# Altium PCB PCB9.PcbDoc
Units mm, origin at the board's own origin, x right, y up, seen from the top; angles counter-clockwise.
Board outline 101.6 x 53.34 mm, 4 copper layers (TOP, GND, SIG, BOTTOM), stack 1.586 mm thick; 105 components, 243 nets, 863 pads, 0 vias.
Unrouted connection lines stored in the file: 305.
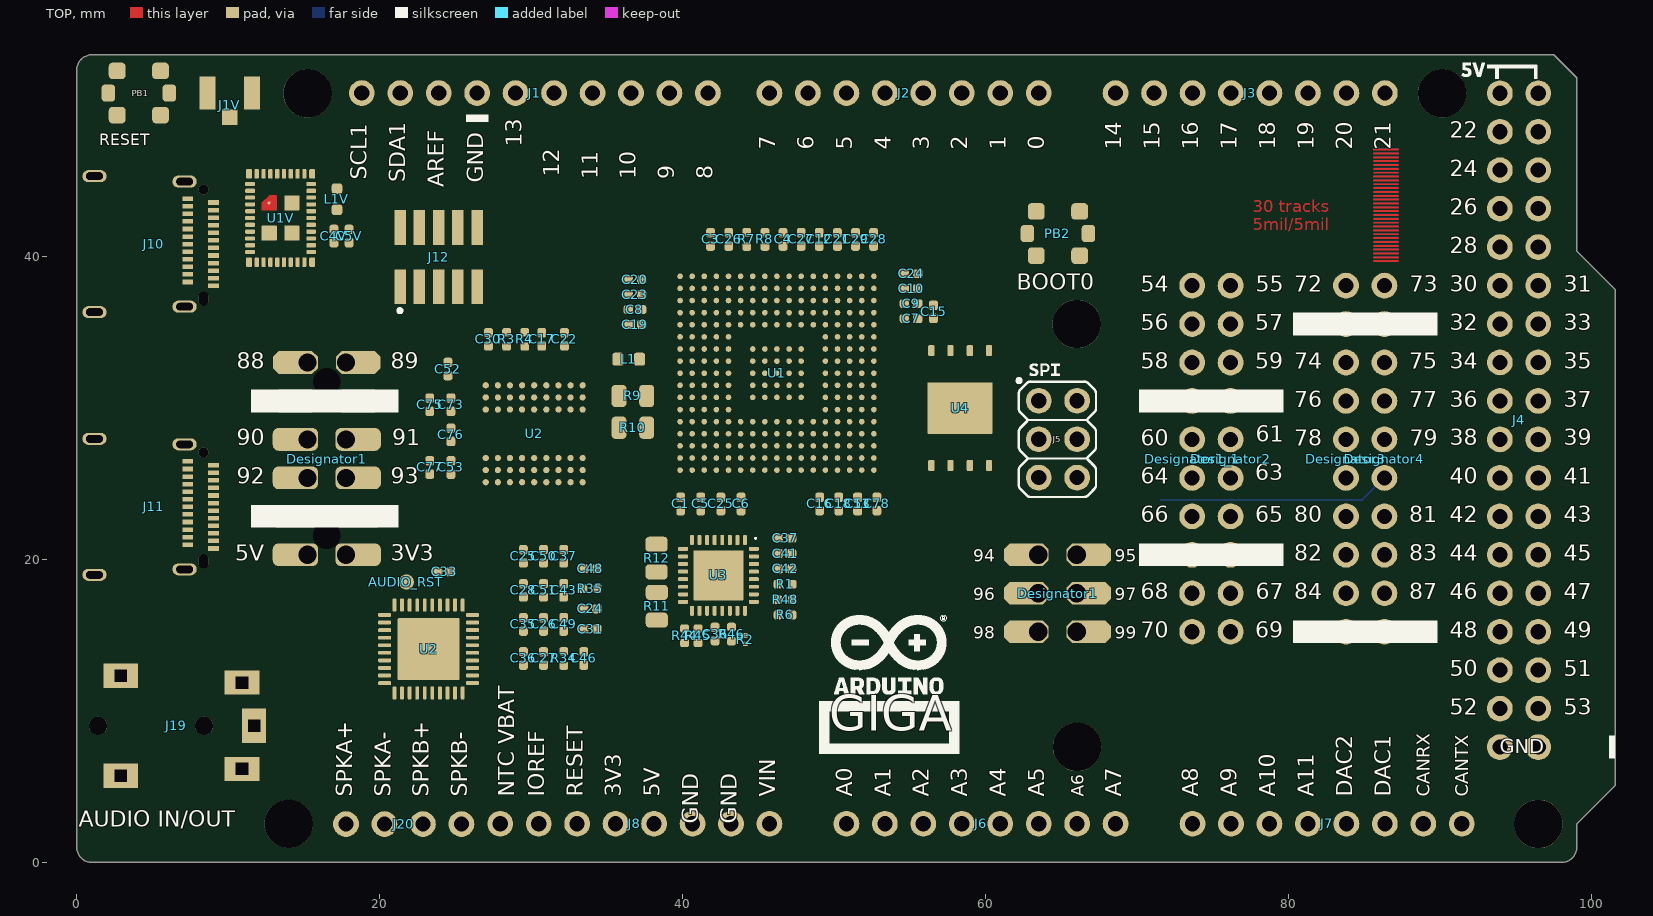
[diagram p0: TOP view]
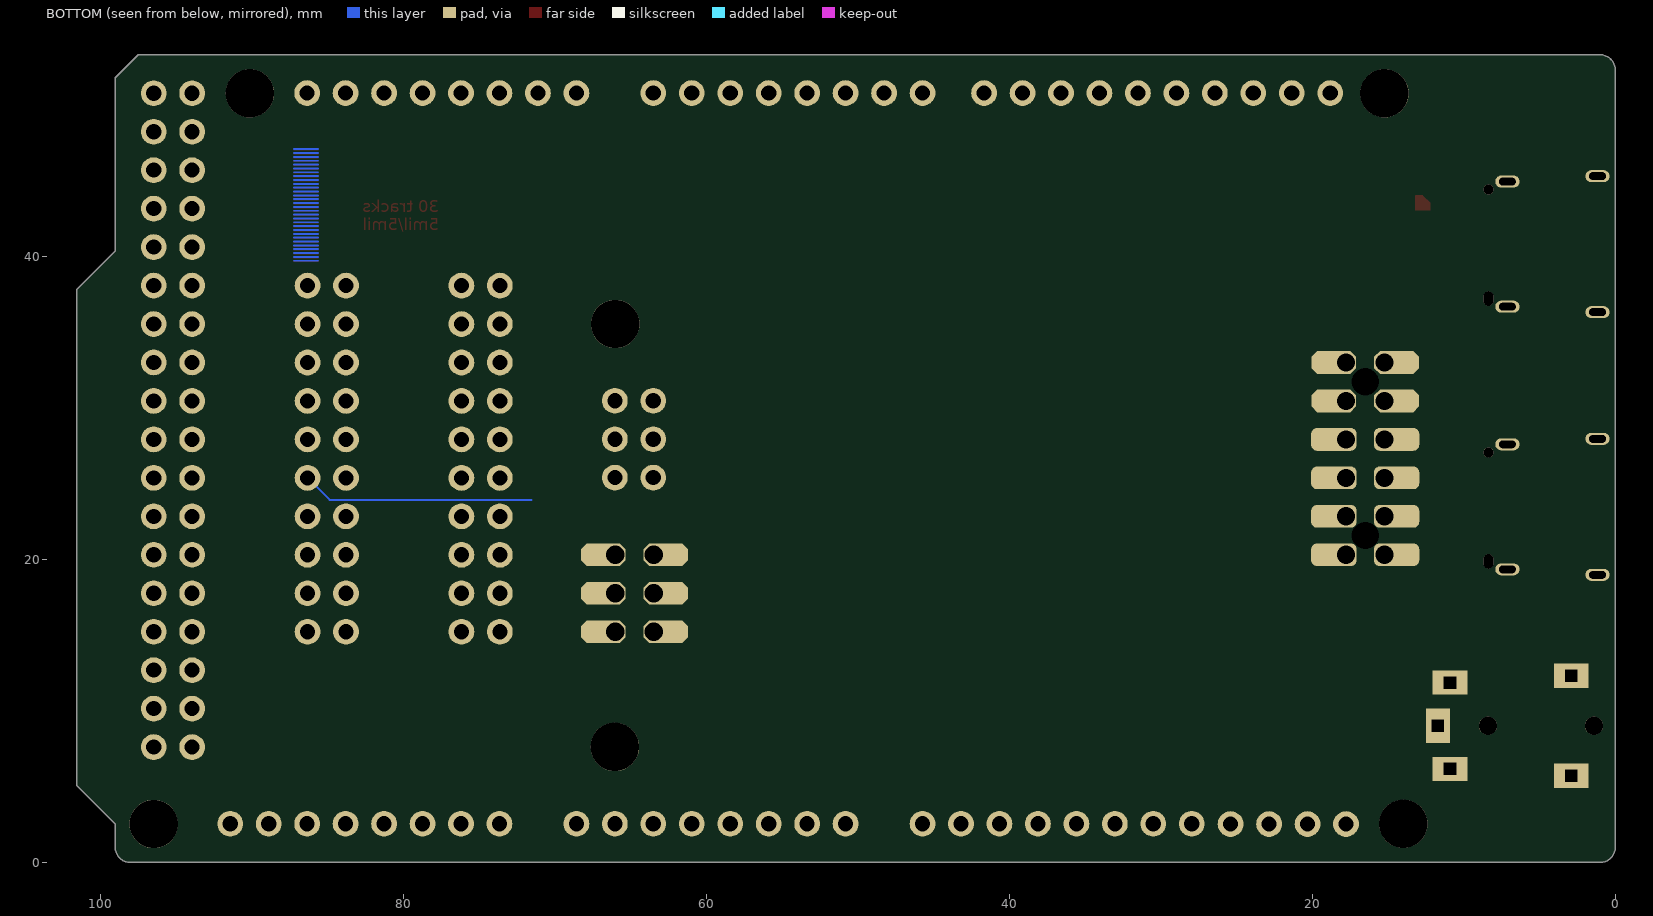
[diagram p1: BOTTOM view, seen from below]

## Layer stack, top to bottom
Top Solder: solder mask 0.0102, Solder Resist, Dk 3.5
TOP: signal copper 0.018
Dielectric 1: prepreg 0.14, PP-014, Dk 4.2
GND: signal copper 0.035
Dielectric2: core 1.2, FR-4, Dk 4.8
SIG: signal copper 0.035
Dielectric3: prepreg 0.14, PP-014, Dk 4.2
BOTTOM: signal copper 0.018
Bottom Solder: solder mask 0.0102, Solder Resist, Dk 3.5

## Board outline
0,1 0,52.34 cw(c1,52.34) 1,53.34 97.536,53.34 99.06,51.816 99.06,40.386 101.6,37.846 101.6,5.08 99.06,2.54 99.06,1 cw(c98.06,1) 98.06,0 1,0 cw(c1,1)

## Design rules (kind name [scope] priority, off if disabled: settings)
BoardOutlineClearance Silks [(OnLayer('Top Overlay') OR OnLayer('Bottom Overlay'))] p1: gap=0.1 ignorepadtopadclearanceinfootprint=FALSE
BoardOutlineClearance [All] p2: gap=0.3 ignorepadtopadclearanceinfootprint=FALSE
Clearance COPPER_0.3mm [All] p1: gap=0.127 ignorepadtopadclearanceinfootprint=FALSE except(0.3: Arc-Fill Arc-Poly Arc-Region Track-Fill Track-Poly Track-Region SMDPad-Fill SMDPad-Poly SMDPad-Region THPad-Fill THPad-Poly THPad-Region Via-Fill Via-Poly Via-Region Fill-Fill Fill-Poly Fill-Region Poly-Poly Poly-Region Region-Region)
Clearance "Generic clearance 0.127mm" [All] p2: gap=0.127 ignorepadtopadclearanceinfootprint=FALSE
ComponentClearance [All] p1: gap=0.2 collisioncheckmode=3 verticalgap=0 showdistances=TRUE
DiffPairsRouting USB [InDifferentialPairClass('USB')] p1: maxlimit=0.254 minlimit=0.15 mostfreqgap=0.254 toplayer_maxgap=0.15 toplayer_prefgap=0.15 toplayer_minwidth=0.15 toplayer_maxwidth=0.21 toplayer_prefwidth=0.2 midlayer2_mingap=0.24 midlayer2_maxgap=0.24 midlayer2_prefgap=0.24 midlayer2_minwidth=0.15 midlayer2_maxwidth=0.15 midlayer2_prefwidth=0.15 bottomlayer_maxgap=0.15 bottomlayer_prefgap=0.15 bottomlayer_minwidth=0.15 bottomlayer_maxwidth=0.21 bottomlayer_prefwidth=0.2 impedanceprofiledriven=TRUE impedanceprofileid={E6B00C31-4C8E-439C-824F-D2B2CDC26F9C} impedanceprofilevalue=90.000000 maxuncoupledlength=12.7
Height [All] p1: minheight=0 maxheight=30 prefheight=12.7
HoleSize [All] p1: absolutevalues=TRUE maxlimit=20 minlimit=0.3 maxpercent=80.000 minpercent=20.000
HoleToHoleClearance [All] p1: gap=0.25 allowstackedmicrovias=FALSE
MinimumAnnularRing [All] p1: minimumring=0.15
PlaneConnect [All] p1: pad.planeconnectstyle=Relief pad.reliefexpansion=0.508 pad.reliefentries=4 pad.reliefconductorwidth=0.254 pad.reliefairgap=0.254 via.planeconnectstyle=Direct via.reliefexpansion=0.508 via.reliefentries=4 via.reliefconductorwidth=0.254 via.reliefairgap=0.254
PolygonConnect [All] p1: thpad.connectstyle=Relief thpad.reliefconductorwidth=0.2 thpad.reliefentries=4 thpad.polygonreliefangle="90 Angle" thpad.airgapwidth=0.254 smdpad.connectstyle=Relief smdpad.reliefconductorwidth=0.2 smdpad.reliefentries=4 smdpad.polygonreliefangle="90 Angle" smdpad.airgapwidth=0.254 via.connectstyle=Direct via.reliefconductorwidth=0.254 via.reliefentries=4 via.polygonreliefangle="90 Angle" via.airgapwidth=0.254
RoomDefinition AUDIO [InComponentClass('AUDIO')] p1: confinementstyle=ConfineIn formatcopy=TRUE lockcomponents=FALSE outline 102.7,0.5 179.2,0.5 179.2,30 102.7,30
RoomDefinition Wifi [InComponentClass('Wifi')] p2: confinementstyle=ConfineIn formatcopy=TRUE lockcomponents=FALSE outline -40.4,-40.4 10.4,-40.4 10.4,-15 -40.4,-15
RoomDefinition TOP [InComponentClass('TOP')] p3: confinementstyle=ConfineIn formatcopy=TRUE lockcomponents=FALSE outline 102.7,1.5 112.4,1.5 112.4,12.5 102.7,12.5
RoomDefinition HEADERS [InComponentClass('HEADERS')] p4: confinementstyle=ConfineIn formatcopy=TRUE lockcomponents=FALSE outline 103.6,3.6 145.6,3.6 145.6,51.6 103.6,51.6
RoomDefinition STM32H747 [InComponentClass('STM32H747')] p5: confinementstyle=ConfineIn formatcopy=TRUE lockcomponents=FALSE outline 57.6,-10.4 61.6,-10.4 61.6,-6.4 57.6,-6.4
RoutingVias StandardVias [All] p1: holewidth=0.2 width=0.4 viastyle="Through Hole" minholewidth=0.2 minwidth=0.4 maxholewidth=0.2 maxwidth=0.4
SMDToCorner [All] p1: distance=39370
SilkToSilkClearance [All] p1: silktosilkclearance=0.2
SilkToSolderMaskClearance [IsPad] p1: minsilkscreentomaskgap=0.15 clearancetoexposedcopper=TRUE
SolderMaskExpansion VIAtented [IsVia] p1: expansion=0.102 istentingtop=TRUE
SolderMaskExpansion [All] p2: expansion=0.05 istentingtop=FALSE
UnRoutedNet [All] p1: checkbadconnections=TRUE
ViasUnderSMD [All] p1: allowed=FALSE
Width StandardTraces [All] p1: maxlimit=5 minlimit=0.127 preferedwidth=0.15
21 further rules are at their usual default settings.

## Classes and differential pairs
component class AUDIO: AUDIO_RST C24 C25 C26 C27 C28 C31 C33 C35 C36 C37 C43 C46 C48 C49 C50 C51 J19 R34 R35 U2
net class "50 ohm": NetC1V_1 NetC2V_1
component class Wifi: R18
component class TOP: PB2
component class HEADERS: J1 J2 J3 J4 J5 J6 J7 J8 J12 J20
component class STM32H747: C1 C3 C4 C5 C6 C7 C8 C9 C10 C12 C13 C15 C16 C17 C18 C19 C20 C21 C22 C23 C24 C25 C26 C27 C28 C29 C30 C36 C37 C41 C42 C51 C52 C53 C73 C75 C76 C77 C78 L1 R1 R2 R3 R4 R6 R7 R8 R9 R10 R11 R12 R44 R45 R46 R48 U1 U2 U3 U4

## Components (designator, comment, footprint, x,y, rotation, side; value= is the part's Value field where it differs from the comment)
AUDIO_RST "CMP-018-0005-A.3" TP-1.00MM 21.77,18.519 r180 top
C1 "CBR04C220F5GAC" CAP-0402 39.88,23.675 r90 top value=22pF
C3 "GRM155R60J106ME05D" CAP-0402 41.859,41.145 r270 top value=10µF
C4 "GRM155R60J225KE95D" CAP-0402 46.644,41.145 r270 top value=2.2µF
C4V "GRM155R60J475ME47D" CAP-0402 16.984,41.367 r270 top value=4.7µF
C5 "GRM155R60J225KE95D" CAP-0402 41.21,23.675 r90 top value=2.2µF
C5V "GRM155R60J475ME47D" CAP-0402 17.984,41.367 r270 top value=4.7µF
C6 "GRM155R60J225KE95D" CAP-0402 43.87,23.675 r90 top value=2.2µF
C7 "GRM155R61H104KE19D" CAP-0402 55.097,35.913 r0 top value=100nF
C8 "GRM155R61H104KE19D" CAP-0402 36.865,36.51 r0 top value=100nF
C9 "GRM155R61H104KE19D" CAP-0402 55.097,36.903 r0 top value=100nF
C10 "GRM155R61H104KE19D" CAP-0402 55.097,37.893 r0 top value=100nF
C12 "CBR04C220F5GAC" CAP-0402 49.036,41.145 r270 top value=22pF
C13 "GRM155R61H104KE19D" CAP-0402 51.581,23.675 r270 top value=100nF
C15 "GRM155R61H104KE19D" CAP-0402 56.579,36.36 r90 top value=100nF
C16 "GRM155R61H104KE19D" CAP-0402 49.06,23.675 r270 top value=100nF
C17 "GRM155R61H104KE19D" CAP-0402 30.709,34.545 r90 top value=100nF
C18 "GRM155R61H104KE19D" CAP-0402 50.321,23.675 r270 top value=100nF
C19 "GRM155R61H104KE19D" CAP-0402 36.865,35.52 r0 top value=100nF
C20 "GRM155R61H104KE19D" CAP-0402 36.865,38.49 r0 top value=100nF
C21 "GRM155R61H104KE19D" CAP-0402 50.232,41.145 r270 top value=100nF
C22 "GRM155R61H104KE19D" CAP-0402 32.209,34.545 r90 top value=100nF
C23 "GRM155R61H104KE19D" CAP-0402 36.865,37.5 r0 top value=100nF
C24 "C0402C105K8PACTU" CAP-0402 33.915,16.74 r180 top value=1µF
C24 "GRM155R61H104KE19D" CAP-0402 55.097,38.883 r0 top value=100nF
C25 "C0402C104K4RACTU" CAP-0402 29.496,20.22 r90 top value=100nF
C25 "GRM155R60J225KE95D" CAP-0402 42.54,23.675 r90 top value=2.2µF
C26 "C0402C104K4RACTU" CAP-0402 30.826,15.72 r90 top value=100nF
C26 "GRM155R60J225KE95D" CAP-0402 43.055,41.145 r270 top value=2.2µF
C27 "C0402C104K4RACTU" CAP-0402 30.826,13.47 r90 top value=100nF
C27 "GRM155R60J225KE95D" CAP-0402 47.84,41.145 r270 top value=2.2µF
C28 "C0402C105K8PACTU" CAP-0402 29.496,17.97 r90 top value=1µF
C28 "GRM155R61H104KE19D" CAP-0402 52.625,41.145 r270 top value=100nF
C29 "GRM155R61H104KE19D" CAP-0402 51.429,41.145 r270 top value=100nF
C30 "GRM155R60J106ME05D" CAP-0402 27.188,34.545 r270 top value=10µF
C31 "C0402C105K8PACTU" CAP-0402 33.915,15.41 r180 top value=1µF
C33 "C0402C105K8PACTU" CAP-0402 24.257,19.185 r180 top value=1µF
C35 "C0402C104K4RACTU" CAP-0402 29.496,15.72 r90 top value=100nF
C36 "C0402C104K4RACTU" CAP-0402 29.496,13.47 r90 top value=100nF
C36 "GRM155R61H104KE19D" CAP-0402 42.155,15.085 r90 top value=100nF
C37 "C0402C104K4RACTU" CAP-0402 32.156,20.22 r90 top value=100nF
C37 "GRM155R61H104KE19D" CAP-0402 46.775,21.41 r180 top value=100nF
C41 "GRM155R61H104KE19D" CAP-0402 46.775,20.397 r180 top value=100nF
C42 "GRM155R61H104KE19D" CAP-0402 46.775,19.383 r180 top value=100nF
C43 "C0402C104K4RACTU" CAP-0402 32.156,17.97 r90 top value=100nF
C46 "GRM1555C1H151FA01D" CAP-0402 33.486,13.47 r90 top value=150pF
C48 "C0402C104K4RACTU" CAP-0402 33.915,19.4 r180 top value=100nF
C49 "C0402C105K8PACTU" CAP-0402 32.156,15.72 r90 top value=1µF
C50 "GRM1555C1H151FA01D" CAP-0402 30.826,20.22 r90 top value=150pF
C51 "C0402C104K4RACTU" CAP-0402 30.826,17.97 r90 top value=100nF
C51 "GRM155R61H104KE19D" CAP-0402 51.563,23.675 r270 top value=100nF
C52 "GRM155R61H104KE19D" CAP-0402 24.512,32.585 r90 top value=100nF
C53 "GRM155R61H104KE19D" CAP-0402 24.712,26.085 r270 top value=100nF
C73 "GRM155R61H104KE19D" CAP-0402 24.712,30.23 r90 top value=100nF
C75 "GRM155R61H104KE19D" CAP-0402 23.312,30.23 r270 top value=100nF
C76 "GRM155R61H104KE19D" CAP-0402 24.712,28.24 r90 top value=100nF
C77 "GRM155R61H104KE19D" CAP-0402 23.312,26.085 r90 top value=100nF
C78 "GRM155R61H104KE19D" CAP-0402 52.842,23.675 r270 top value=100nF
Designator1 "Comment" HLE-103-02-F-DV 64.77,17.779 r270 top
Designator1 "Comment" HLE-106-02-F-DV 16.51,26.669 r270 top
Designator1_1 "Comment" "PIN HEADER 2.54mm VERT. 1x10POS" 73.66,26.667 r270 top
Designator2 "Comment" "PIN HEADER 2.54mm VERT. 1x10POS" 76.2,26.667 r270 top
Designator3 "Comment" "PIN HEADER 2.54mm VERT. 1x10POS" 83.82,26.667 r270 top
Designator4 "Comment" "PIN HEADER 2.54mm VERT. 1x10POS" 86.36,26.667 r270 top
J1 "HEADER TH 2.54mm VERT. 1x010POS" "PIN HEADER 2.54mm VERT. 1x10POS" 30.252,50.813 r0 top
J1V "U.FL-R-SMT-1(60)" U.FL-R-SMT-1(60)-1 10.1,50.813 r0 top
J2 "HEADER TH 2.54mm VERT. 1x008POS" "PIN HEADER 2.54mm VERT. 1x8POS" 54.636,50.813 r0 top
J3 "HEADER TH 2.54mm VERT. 1x008POS" "PIN HEADER 2.54mm VERT. 1x8POS" 77.496,50.813 r0 top
J4 "HEADER TH 2.54mm VERT. 2x018POS" "PIN HEADER 2.54mm VERT. 2x6POS" 95.25,29.209 r270 top
J5 "HEADER TH 2.54mm VERT. 2x003POS" "HEADER TH 2.54mm VERT. 2x003POS-Footprint-1" 64.796,27.953 r270 top
J6 "HEADER TH 2.54mm VERT. 1x008POS" "PIN HEADER 2.54mm VERT. 1x8POS" 59.716,2.553 r0 top
J7 "HEADER TH 2.54mm VERT. 1x008POS" "PIN HEADER 2.54mm VERT. 1x8POS" 82.576,2.553 r0 top
J8 "HEADER TH 2.54mm VERT. 1x008POS" "PIN HEADER 2.54mm VERT. 1x8POS" 36.856,2.553 r0 top
J10 "12401598E4#2A" 12401598E4#2A 5.1,40.835 r270 top (schematic designator J1)
J11 "12401598E4#2A" 12401598E4#2A 5.1,23.485 r270 top (schematic designator J1)
J12 "FTSH-105-01-F-DV" FTSH-105-01-F-DV-Footprint-1 23.902,39.973 r0 top
J19 "54-00174" 54-00174-Footprint-1 11.71,9.03 r0 top
J20 "HEADER TH 2.54mm VERT. 1x004POS" "PIN HEADER 2.54mm VERT. 1x4POS-Footprint-1" 21.59,2.539 r0 top
L1 "FBMJ1608HM180NTR" L-0603 36.45,33.24 r0 top
L1V "LQM18PN2R2MGHD" FP-LQM18PN_GH-IPC_C 17.184,43.802 r270 top value=2.2uH
PB1 "PTS820J25KSMTRLFS" C&K_PTS820_NO_HOLES-1 4.1,50.813 r180 top
PB2 "PTS820J25KSMTRLFS" C&K_PTS820_NO_HOLES-1 64.796,41.533 r180 top
R1 "CRCW0402100KFKEDC" RES-0402 46.775,18.37 r0 top value=100k
R2 "RC0201FR-078K06L" RES-0201 44.155,14.715 r270 top value=8.06k
R3 "CRCW04020000Z0EDC" RES-0402 28.388,34.545 r90 top value=0
R4 "CRCW0402100KFKEDC" RES-0402 29.588,34.545 r90 top value=100k
R6 "CRCW0402100KFKEDC" RES-0402 46.775,16.343 r180 top value=100k
R7 "CRCW04020000Z0EDC" RES-0402 44.251,41.145 r270 top value=0
R8 "CRCW04020000Z0EDC" RES-0402 45.448,41.145 r270 top value=0
R9 "CRCW08050000Z0EB" RES-0805 36.725,30.81 r180 top value=0
R10 "CRCW08050000Z0EB" RES-0805 36.725,28.71 r180 top value=0
R11 "CRCW08050000Z0EB" RES-0805 38.309,16.92 r90 top value=0
R12 "CRCW08050000Z0EB" RES-0805 38.291,20.101 r270 top value=0
R34 "CRCW04022K00JNED" RES-0402 32.156,13.47 r90 top value=2k
R35 "CRCW04022K00JNED" RES-0402 33.915,18.07 r180 top value=2k
R44 "CRCW04020000Z0EDC" RES-0402 40.14,14.97 r270 top value=0
R45 "CRCW04020000Z0EDC" RES-0402 41.032,14.97 r270 top value=0
R46 "CRCW040210K0FKED" RES-0402 43.24,15.085 r270 top value=10k
R48 "CRCW0402100KFKEDC" RES-0402 46.775,17.357 r0 top value=100k
U1 "STM32H747XIH6" STM32H747XIH6-Footprint-1 46.24,32.31 r270 top
U1V "LBEE5KL1DX-883" LBEE5KL1DX-883 13.46,42.559 r270 top
U2 "CS42L52-CNZ" QFN127P600-8N 23.231,14.095 r90 top
U2 "AS4C4M16SA-6BIN" AS4C4M16SA-7BCN-Footprint-1 30.209,28.31 r0 top
U3 "USB3320C-EZK-TR" USB3320C-EZK-Footprint-1 42.378,18.958 r180 top
U4 "MX25L12833FZ2I-10G" WSON8-1 58.34,30.01 r180 top

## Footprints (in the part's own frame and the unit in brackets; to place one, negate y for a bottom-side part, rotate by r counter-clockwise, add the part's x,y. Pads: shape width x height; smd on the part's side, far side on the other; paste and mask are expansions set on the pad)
54-00174-Footprint-1 [mm]
  rect 1.6x2.3 hole 0.8 square unplated: 1(0,0)
  rect 2.3x1.6 hole 0.8 square unplated: 2(-0.8,2.85) 3(-0.8,-2.85) 4(-8.8,-3.3) 4(-8.8,3.3)
  round 1.2 hole 1.2 unplated mask+0.2: NC1(-3.3,0) NC2(-10.3,0)
  body extent -14.74,-3.5 0.26,3.6, height 6.13
12401598E4#2A [mm]
  oval 1x1.8 on Top Paste: 0(-4.499,-3.932) 0(-4.131,2.023) 0(4.131,2.026) 0(4.461,-3.925)
  round 0.65 hole 0.65 unplated mask+0.05: 0(-3.6,3.27)
  oval 0.95x0.65 hole 0.65 slot 0.95 at 0 deg unplated mask+0: 0(3.6,3.27)
  rect 0.3x0.7 smd mask+0.04: A1(-2.75,3.93) A2(-2.25,3.93) A3(-1.75,3.93) A4(-1.25,3.93) A5(-0.75,3.93) A6(-0.25,3.93) A7(0.25,3.93) A8(0.75,3.93) A9(1.25,3.93) A10(1.75,3.93) B1(2.5,2.23) B2(2,2.23) B3(1.5,2.23) B4(1,2.23) B5(0.5,2.23) B6(0,2.23) B7(-0.5,2.23) B8(-1,2.23) B9(-1.5,2.23) B10(-2,2.23) B11(-2.5,2.23) B12(-3,2.23)
  rect 0.3x0.7 smd mask+0.03: A11(2.25,3.93) A12(2.75,3.93)
  oval 0.8x1.6 hole 0.5 slot 1.1 at 90 deg: "SHIELD 1"(-4.13,2.02) "SHIELD 2"(4.13,2.02) "SHIELD 3"(-4.49,-3.93) "SHIELD 4"(4.49,-3.93)
  body extent -4.6,-6.3 4.6,4.25, height 3.3
AS4C4M16SA-7BCN-Footprint-1 [mm]
  round 0.41 smd: A1(-3.2,-3.2) A2(-3.2,-2.4) A3(-3.2,-1.6) A7(-3.2,1.6) A8(-3.2,2.4) A9(-3.2,3.2) B1(-2.4,-3.2) B2(-2.4,-2.4) B3(-2.4,-1.6) B7(-2.4,1.6) B8(-2.4,2.4) B9(-2.4,3.2) C1(-1.6,-3.2) C2(-1.6,-2.4) C3(-1.6,-1.6) C7(-1.6,1.6) C8(-1.6,2.4) C9(-1.6,3.2) D1(-0.8,-3.2) D2(-0.8,-2.4) D3(-0.8,-1.6) D7(-0.8,1.6) D8(-0.8,2.4) D9(-0.8,3.2) E1(0,-3.2) E2(0,-2.4) E3(0,-1.6) E7(0,1.6) E8(0,2.4) E9(0,3.2) F1(0.8,-3.2) F2(0.8,-2.4) F3(0.8,-1.6) F7(0.8,1.6) F8(0.8,2.4) F9(0.8,3.2) G1(1.6,-3.2) G2(1.6,-2.4) G3(1.6,-1.6) G7(1.6,1.6) G8(1.6,2.4) G9(1.6,3.2) H1(2.4,-3.2) H2(2.4,-2.4) H3(2.4,-1.6) H7(2.4,1.6) H8(2.4,2.4) H9(2.4,3.2) J1(3.2,-3.2) J2(3.2,-2.4) J3(3.2,-1.6) J7(3.2,1.6) J8(3.2,2.4) J9(3.2,3.2)
  body extent -4,-4 4,4, height 1.15
C&K_PTS820_NO_HOLES-1 [mm]
  rrect49% 0.89x1.12 smd: 5(-2.015,0) 6(2.015,0)
  rrect46% 1.11x1.09 smd: PAD(-1.434,1.46) PAD(-1.434,-1.46) PAD(1.434,1.46) PAD(1.434,-1.46)
  body extent -2.25,-1.45 2.25,1.45, height 2
CAP-0402 [mm] "Chip Capacitor, 2-Leads, Body  0402 (in) 1005 (mm), IPC Medium Density"
  rrect52% 0.63x0.58 smd mask+0: 1(-0.435,0) 2(0.435,0)
  body extent -0.5,-0.25 0.5,0.25, height 0.5
FP-LQM18PN_GH-IPC_C [mm]
  rrect50% 0.7x0.7 smd: 1(-0.7,0) 2(0.7,0)
  body extent -0.8,-0.4 0.8,0.4, height 1
FTSH-105-01-F-DV-Footprint-1 [mm]
  rect 0.76x2.3 smd: 1(-2.54,-1.95) 2(-2.54,1.95) 3(-1.27,-1.95) 4(-1.27,1.95) 5(0,-1.95) 6(0,1.95) 7(1.27,-1.95) 8(1.27,1.95) 9(2.54,-1.95) 10(2.54,1.95)
  body extent -3.17,-2.92 3.17,2.92, height 5.98
"HEADER TH 2.54mm VERT. 2x003POS-Footprint-1" [mm]
  round 1.7 hole 1 mask+0.2: 1(-2.54,-1.27) 2(-2.54,1.27) 3(0,-1.27) 4(0,1.27) 5(2.54,-1.27) 6(2.54,1.27)
HLE-103-02-F-DV [mm]
  oct 1.5x2.95 hole 1.2 copper offset 0,-0.8 mask+0.02: 1(-2.54,-1.27) 3(0,-1.27) 5(2.54,-1.27)
  oct 1.5x2.95 hole 1.2 copper offset 0,0.8 mask+0.02: 2(-2.54,1.27) 4(0,1.27) 6(2.54,1.27)
  body extent -3.81,-3.29 3.81,3.29, height 3.71
HLE-106-02-F-DV [mm]
  round 0 hole 1.8 unplated paste-5: 0(-5.08,0) 0(5.08,0)
  oct 1.5x2.95 hole 1.2 copper offset 0,-0.8 mask+0.02: 1(-6.35,-1.27) 3(-3.81,-1.27)
  oct 1.5x2.95 hole 1.2 copper offset 0,0.8 mask+0.02: 2(-6.35,1.27) 4(-3.81,1.27)
  rrect50% 1.5x3 hole 1.2 copper offset 0,-0.8 mask+0.02: 5(-1.27,-1.27) 7(1.27,-1.27) 9(3.81,-1.27) 11(6.35,-1.27)
  rrect50% 1.5x3 hole 1.2 copper offset 0,0.8 mask+0.02: 6(-1.27,1.27) 8(1.27,1.27) 10(3.81,1.27) 12(6.35,1.27)
  body extent -7.62,-3.29 7.62,3.29, height 3.71
L-0603 [mm] "Chip Inductor - Body 0603 imperial,1.6x0.8mm, IPC High Density"
  rrect51% 0.75x0.87 smd mask+0: 1(-0.71,0) 2(0.71,0)
  body extent -0.8,-0.4 0.8,0.4, height 0.8
LBEE5KL1DX-883 [mm]
  rrect50% 0.28x0.64 smd mask+0.05: 1(-2.25,-2.015) 2(-1.8,-2.015) 3(-1.35,-2.015) 4(-0.9,-2.015) 5(-0.45,-2.015) 6(0,-2.015) 7(0.45,-2.015) 8(0.9,-2.015) 9(1.35,-2.015) 10(1.8,-2.015) 11(2.25,-2.015) 22(2.25,2.015) 23(1.8,2.015) 24(1.35,2.015) 25(0.9,2.015) 26(0.45,2.015) 27(0,2.015) 28(-0.45,2.015) 29(-0.9,2.015) 30(-1.35,2.015) 31(-1.8,2.015) 32(-2.25,2.015)
  rrect50% 0.64x0.4 smd mask+0.05: 12(2.915,-2.087) 21(2.915,2.087) 33(-2.915,2.087) 42(-2.915,-2.087)
  rrect50% 0.64x0.28 smd mask+0.05: 13(2.915,-1.575) 14(2.915,-1.125) 15(2.915,-0.675) 16(2.915,-0.225) 17(2.915,0.225) 18(2.915,0.675) 19(2.915,1.125) 20(2.915,1.575) 34(-2.915,1.575) 35(-2.915,1.125) 36(-2.915,0.675) 37(-2.915,0.225) 38(-2.915,-0.225) 39(-2.915,-0.675) 40(-2.915,-1.125) 41(-2.915,-1.575)
  round 0.2 smd paste+0 mask+0.05: 43(-1,-0.75)
  rrect10% 1x1 smd mask+0.05: 44(1,-0.75) 45(-1,0.75) 46(1,0.75)
  TOP region: -1.485,-0.765 -1.496,-0.748 -1.5,-0.729 -1.5,-0.729 -1.5,-0.3 -1.496,-0.281 -1.485,-0.265 -1.469,-0.254 -1.45,-0.25 -1.45,-0.25 -0.55,-0.25 -0.531,-0.254 -0.515,-0.265 -0.504,-0.281 -0.5,-0.3 -0.5,-0.3 -0.5,-1.2 -0.504,-1.219 -0.515,-1.235 -0.531,-1.246 -0.55,-1.25 -0.55,-1.25 -0.979,-1.25 -0.998,-1.246 -1.015,-1.235 -1.015,-1.235
  body extent -3.47,-2.57 3.48,2.58, height 1.1
"PIN HEADER 2.54mm VERT. 1x4POS-Footprint-1" [mm]
  round 1.7 hole 1 mask+0.2: 1(-3.81,0) 2(-1.27,0) 3(1.27,0) 4(3.81,0)
"PIN HEADER 2.54mm VERT. 1x8POS" [mm]
  round 1.7 hole 1 mask+0.2: 1(-8.89,0) 2(-6.35,0) 3(-3.81,0) 4(-1.27,0) 5(1.27,0) 6(3.81,0) 7(6.35,0) 8(8.89,0)
"PIN HEADER 2.54mm VERT. 1x10POS" [mm]
  round 1.7 hole 1 mask+0.2: 1(-11.43,0) 2(-8.89,0) 3(-6.35,0) 4(-3.81,0) 5(-1.27,0) 6(1.27,0) 7(3.81,0) 8(6.35,0) 9(8.89,0) 10(11.43,0)
"PIN HEADER 2.54mm VERT. 2x6POS" [mm]
  round 1.7 hole 1 mask+0.2: 1(-21.59,-1.27) 2(-21.59,1.27) 3(-19.05,-1.27) 4(-19.05,1.27) 5(-16.51,-1.27) 6(-16.51,1.27) 7(-13.97,-1.27) 8(-13.97,1.27) 9(-11.43,-1.27) 10(-11.43,1.27) 11(-8.89,-1.27) 12(-8.89,1.27) 13(-6.35,-1.27) 14(-6.35,1.27) 15(-3.81,-1.27) 16(-3.81,1.27) 17(-1.27,-1.27) 18(-1.27,1.27) 19(1.27,-1.27) 20(1.27,1.27) 21(3.81,-1.27) 22(3.81,1.27) 23(6.35,-1.27) 24(6.35,1.27) 25(8.89,-1.27) 26(8.89,1.27) 27(11.43,-1.27) 28(11.43,1.27) 29(13.97,-1.27) 30(13.97,1.27) 31(16.51,-1.27) 32(16.51,1.27) 33(19.05,-1.27) 34(19.05,1.27) 35(21.59,-1.27) 36(21.59,1.27)
QFN127P600-8N [mm]
  rrect50% 0.85x0.25 smd mask+0.05: 1(-2.9,2.25) 2(-2.9,1.75) 3(-2.9,1.25) 4(-2.9,0.75) 5(-2.9,0.25) 6(-2.9,-0.25) 7(-2.9,-0.75) 8(-2.9,-1.25) 9(-2.9,-1.75) 10(-2.9,-2.25) 21(2.9,-2.25) 22(2.9,-1.75) 23(2.9,-1.25) 24(2.9,-0.75) 25(2.9,-0.25) 26(2.9,0.25) 27(2.9,0.75) 28(2.9,1.25) 29(2.9,1.75) 30(2.9,2.25)
  rrect50% 0.25x0.85 smd mask+0.05: 11(-2.25,-2.9) 12(-1.75,-2.9) 13(-1.25,-2.9) 14(-0.75,-2.9) 15(-0.25,-2.9) 16(0.25,-2.9) 17(0.75,-2.9) 18(1.25,-2.9) 19(1.75,-2.9) 20(2.25,-2.9) 31(2.25,2.9) 32(1.75,2.9) 33(1.25,2.9) 34(0.75,2.9) 35(0.25,2.9) 36(-0.25,2.9) 37(-0.75,2.9) 38(-1.25,2.9) 39(-1.75,2.9) 40(-2.25,2.9)
  rrect5% 4.1x4.1 smd paste-5 mask+0.05: 41(0,0)
  body extent -3,-3 3,3, height 1
RES-0201 [mm] "Chip Resistor, 2-Leads, Body 0201 (in) 0603 (mm) IPC Medium Density"
  rrect52% 0.31x0.34 smd mask+0: 1(-0.275,0) 2(0.275,0)
  body extent -0.3,-0.15 0.3,0.15, height 0.24
RES-0402 [mm] "Chip Resistor, 2-Leads, Body  0402 (in) 1005 (mm), IPC Medium Density"
  rrect51% 0.55x0.58 smd mask+0: 1(-0.475,0) 2(0.475,0)
  body extent -0.5,-0.25 0.5,0.25, height 0.34
RES-0805 [mm] "Chip Resistor - Body 0805 imperial, 2.0x1.2mm, IPC Medium Density"
  rrect51% 0.99x1.47 smd paste-1.47 mask+0: 1(-0.915,0) 2(0.915,0)
  body extent -1,-0.62 1,0.63, height 0.58
STM32H747XIH6-Footprint-1 [mm]
  round 0.37 smd: A1(-6.4,-6.4) A2(-6.4,-5.6) A3(-6.4,-4.8) A4(-6.4,-4) A5(-6.4,-3.2) A6(-6.4,-2.4) A7(-6.4,-1.6) A8(-6.4,-0.8) A9(-6.4,0) A10(-6.4,0.8) A11(-6.4,1.6) A12(-6.4,2.4) A13(-6.4,3.2) A14(-6.4,4) A15(-6.4,4.8) A16(-6.4,5.6) A17(-6.4,6.4) B1(-5.6,-6.4) B2(-5.6,-5.6) B3(-5.6,-4.8) B4(-5.6,-4) B5(-5.6,-3.2) B6(-5.6,-2.4) B7(-5.6,-1.6) B8(-5.6,-0.8) B9(-5.6,0) B10(-5.6,0.8) B11(-5.6,1.6) B12(-5.6,2.4) B13(-5.6,3.2) B14(-5.6,4) B15(-5.6,4.8) B16(-5.6,5.6) B17(-5.6,6.4) C1(-4.8,-6.4) C2(-4.8,-5.6) C3(-4.8,-4.8) C4(-4.8,-4) C5(-4.8,-3.2) C6(-4.8,-2.4) C7(-4.8,-1.6) C8(-4.8,-0.8) C9(-4.8,0) C10(-4.8,0.8) C11(-4.8,1.6) C12(-4.8,2.4) C13(-4.8,3.2) C14(-4.8,4) C15(-4.8,4.8) C16(-4.8,5.6) C17(-4.8,6.4) D1(-4,-6.4) D2(-4,-5.6) D3(-4,-4.8) D4(-4,-4) D5(-4,-3.2) D6(-4,-2.4) D7(-4,-1.6) D8(-4,-0.8) D9(-4,0) D10(-4,0.8) D11(-4,1.6) D12(-4,2.4) D13(-4,3.2) D14(-4,4) D15(-4,4.8) D16(-4,5.6) D17(-4,6.4) E1(-3.2,-6.4) E2(-3.2,-5.6) E3(-3.2,-4.8) E4(-3.2,-4) E5(-3.2,-3.2) E6(-3.2,-2.4) E7(-3.2,-1.6) E8(-3.2,-0.8) E9(-3.2,0) E10(-3.2,0.8) E11(-3.2,1.6) E12(-3.2,2.4) E13(-3.2,3.2) E14(-3.2,4) E15(-3.2,4.8) E16(-3.2,5.6) E17(-3.2,6.4) F1(-2.4,-6.4) F2(-2.4,-5.6) F3(-2.4,-4.8) F4(-2.4,-4) F5(-2.4,-3.2) F13(-2.4,3.2) F14(-2.4,4) F15(-2.4,4.8) F16(-2.4,5.6) F17(-2.4,6.4) G1(-1.6,-6.4) G2(-1.6,-5.6) G3(-1.6,-4.8) G4(-1.6,-4) G5(-1.6,-3.2) G7(-1.6,-1.6) G8(-1.6,-0.8) G9(-1.6,0) G10(-1.6,0.8) G11(-1.6,1.6) G13(-1.6,3.2) G14(-1.6,4) G15(-1.6,4.8) G16(-1.6,5.6) G17(-1.6,6.4) H1(-0.8,-6.4) H2(-0.8,-5.6) H3(-0.8,-4.8) H4(-0.8,-4) H5(-0.8,-3.2) H7(-0.8,-1.6) H8(-0.8,-0.8) H9(-0.8,0) H10(-0.8,0.8) H11(-0.8,1.6) H13(-0.8,3.2) H14(-0.8,4) H15(-0.8,4.8) H16(-0.8,5.6) H17(-0.8,6.4) J1(0,-6.4) J2(0,-5.6) J3(0,-4.8) J4(0,-4) J5(0,-3.2) J7(0,-1.6) J8(0,-0.8) J9(0,0) J10(0,0.8) J11(0,1.6) J13(0,3.2) J14(0,4) J15(0,4.8) J16(0,5.6) J17(0,6.4) K1(0.8,-6.4) K2(0.8,-5.6) K3(0.8,-4.8) K4(0.8,-4) K5(0.8,-3.2) K7(0.8,-1.6) K8(0.8,-0.8) K9(0.8,0) K10(0.8,0.8) K11(0.8,1.6) K13(0.8,3.2) K14(0.8,4) K15(0.8,4.8) K16(0.8,5.6) K17(0.8,6.4) L1(1.6,-6.4) L2(1.6,-5.6) L3(1.6,-4.8) L4(1.6,-4) L5(1.6,-3.2) L7(1.6,-1.6) L8(1.6,-0.8) L9(1.6,0) L10(1.6,0.8) L11(1.6,1.6) L13(1.6,3.2) L14(1.6,4) L15(1.6,4.8) L16(1.6,5.6) L17(1.6,6.4) M1(2.4,-6.4) M2(2.4,-5.6) M3(2.4,-4.8) M4(2.4,-4) M5(2.4,-3.2) M13(2.4,3.2) M14(2.4,4) M15(2.4,4.8) M16(2.4,5.6) M17(2.4,6.4) N1(3.2,-6.4) N2(3.2,-5.6) N3(3.2,-4.8) N4(3.2,-4) N5(3.2,-3.2) N6(3.2,-2.4) N7(3.2,-1.6) N8(3.2,-0.8) N9(3.2,0) N10(3.2,0.8) N11(3.2,1.6) N12(3.2,2.4) N13(3.2,3.2) N14(3.2,4) N15(3.2,4.8) N16(3.2,5.6) N17(3.2,6.4) P1(4,-6.4) P2(4,-5.6) P3(4,-4.8) P4(4,-4) P5(4,-3.2) P6(4,-2.4) P7(4,-1.6) P8(4,-0.8) P9(4,0) P10(4,0.8) P11(4,1.6) P12(4,2.4) P13(4,3.2) P14(4,4) P15(4,4.8) P16(4,5.6) P17(4,6.4) R1(4.8,-6.4) R2(4.8,-5.6) R3(4.8,-4.8) R4(4.8,-4) R5(4.8,-3.2) R6(4.8,-2.4) R7(4.8,-1.6) R8(4.8,-0.8) R9(4.8,0) R10(4.8,0.8) R11(4.8,1.6) R12(4.8,2.4) R13(4.8,3.2) R14(4.8,4) R15(4.8,4.8) R16(4.8,5.6) R17(4.8,6.4) T1(5.6,-6.4) T2(5.6,-5.6) T3(5.6,-4.8) T4(5.6,-4) T5(5.6,-3.2) T6(5.6,-2.4) T7(5.6,-1.6) T8(5.6,-0.8) T9(5.6,0) T10(5.6,0.8) T11(5.6,1.6) T12(5.6,2.4) T13(5.6,3.2) T14(5.6,4) T15(5.6,4.8) T16(5.6,5.6) T17(5.6,6.4) U1(6.4,-6.4) U2(6.4,-5.6) U3(6.4,-4.8) U4(6.4,-4) U5(6.4,-3.2) U6(6.4,-2.4) U7(6.4,-1.6) U8(6.4,-0.8) U9(6.4,0) U10(6.4,0.8) U11(6.4,1.6) U12(6.4,2.4) U13(6.4,3.2) U14(6.4,4) U15(6.4,4.8) U16(6.4,5.6) U17(6.4,6.4)
  body extent -7,-7 7,7, height 1.06
TP-1.00MM [mm]
  rrect100% 1x1 smd paste-2.54: X(0,0)
U.FL-R-SMT-1(60)-1 [mm]
  rect 1.05x2.2 smd paste-3: GND(-1.475,0) GND(1.475,0)
  rect 1.05x1 smd paste-3: SIG(0,-1.6)
  body extent -1.5,-1.55 1.5,1.55, height 1.25
USB3320C-EZK-Footprint-1 [mm]
  rrect54% 0.26x0.66 smd paste+0 mask+0: 1(-1.75,-2.335) 2(-1.25,-2.335) 3(-0.75,-2.335) 4(-0.25,-2.335) 5(0.25,-2.335) 6(0.75,-2.335) 7(1.25,-2.335) 8(1.75,-2.335) 17(1.75,2.335) 18(1.25,2.335) 19(0.75,2.335) 20(0.25,2.335) 21(-0.25,2.335) 22(-0.75,2.335) 23(-1.25,2.335) 24(-1.75,2.335)
  rrect54% 0.66x0.26 smd paste+0 mask+0: 9(2.335,-1.75) 10(2.335,-1.25) 11(2.335,-0.75) 12(2.335,-0.25) 13(2.335,0.25) 14(2.335,0.75) 15(2.335,1.25) 16(2.335,1.75) 25(-2.335,1.75) 26(-2.335,1.25) 27(-2.335,0.75) 28(-2.335,0.25) 29(-2.335,-0.25) 30(-2.335,-0.75) 31(-2.335,-1.25) 32(-2.335,-1.75)
  rrect3% 3.3x3.3 smd paste-3.3 mask+0: 33(0,0)
  silkscreen extent -2.5,-2.5 -2.4,-2.4, body extent -2.5,-2.5 2.5,2.5, height 0.85
WSON8-1 [mm]
  rrect52% 0.42x0.74 smd paste+0 mask+0: 1(-1.905,-3.795) 2(-0.635,-3.795) 3(0.635,-3.795) 4(1.905,-3.795) 5(1.905,3.795) 6(0.635,3.795) 7(-0.635,3.795) 8(-1.905,3.795)
  rrect3% 4.3x3.4 smd paste-4.3 mask+0: 9(0,0)
  body extent -3,-4 3,4, height 0.75

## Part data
AUDIO_RST: library part UT0013-A.2, "Test point 1.00mm"
C1 C12: library part C0028-A.9, "CAP CHIP 0402 22pF 50V C0G 1%", Case Code (Imperial)=0402, Case Code (Metric)=1005, Dielectric=C0G, Manufacturer=KEMET, Manufacturer 2=AVX, Manufacturer Part Number 2=04025U220FAT2A, Tolerance=1%, Voltage=50V
C3 C30: library part C0091-A.8, "CAP CHIP 0402 10UF X5R 6.3V 20%", Case Code (Imperial)=0402, Case Code (Metric)=1005, Dielectric=X5R, Manufacturer=Murata, Tolerance=20%, Voltage=6.3V
C4 C5 C6 C25 C26 C27: library part C0031-A.9, "CAP CHIP 0402 2.2uF 6.3V X5R 10%", Case Code (Imperial)=0402, Case Code (Metric)=1005, Dielectric=X5R, Manufacturer=Murata, Tolerance=10%, Voltage=6.3V
C4V C5V: library part C0037-A.9, "CAP CHIP 0402 4.7uF 6V3 X5R 20%", Case Code (Imperial)=0402, Case Code (Metric)=1005, Dielectric=X5R, Manufacturer=Murata, Tolerance=20%, Voltage=6.3V
C7 C8 C9 C10 C13 C15 C16 C17 C18 C19 C20 C21 C22 C23 C24 C28 C29 C36 C37 C41 C42 C51 C52 C53 C73 C75 C76 C77 C78: library part C0015-A.9, "CAP CHIP 0402 100nF 50V X5R 10%", Case Code (Imperial)=0402, Case Code (Metric)=1005, Dielectric=X5R, Manufacturer=Murata, Tolerance=10%, Voltage=50V
C24 C28 C31 C33 C49: library part C0017-A.9, "CAP CHIP 0402 1uF 10V X5R 10%", Case Code (Imperial)=0402, Case Code (Metric)=1005, Dielectric=X5R, Manufacturer=KEMET, Manufacturer 2=AVX, Manufacturer Part Number 2=GRM155R61A105KE15D, Tolerance=10%, Voltage=10V
C25 C26 C27 C35 C36 C37 C43 C48 C51: library part C0012-A.9, "CAP CHIP 0402 100nF 16V X7R 10%", Case Code (Imperial)=0402, Case Code (Metric)=1005, Dielectric=X7R, Manufacturer=KEMET, Manufacturer 2=AVX, Manufacturer Part Number 2=0402YC104KAT2A, Tolerance=10%, Voltage=16V
C46 C50: library part C0074-A.7, "CAP CHIP 0402 150PF 50V C0G 1%", Case Code (Imperial)=0402, Case Code (Metric)=1005, Dielectric=C0G, Manufacturer=Murata, Tolerance=1%, Voltage=50V
J1: library part J0169-A.5
J1V: library part J0042-A.4, "CONN Micro UFL NO PASTE", Manufacturer=Hirose
J2 J3 J6 J7 J8: library part J0171-A.2
J4: library part J0239-A.1
J5: library part J0240-A.2
J10 J11: library part J0220-A.5, "CONN RCP USB3.1 TYPEC 24P SMD RA", Flammability Rating="UL94 V-0", Manufacturer="Amphenol ICC (Commercial Products)"
J12: library part J0089-A.6, "CONN HEADER SMD 10POS 2x5 1.27MM JTAG", Color=Black, Current Rating=1.75A, Manufacturer=Samtec, Max Operating Temperature=125°C, Min Operating Temperature=-55°C, Package Quantity=1
J19: library part J0244-A.1, "Conn Jack 4 POLES 3.5mm R/a", Manufacturer="Tensility International Corp"
J20: library part J0162-A.4
L1: library part I0004-A.3, "FERRITE SMD 0603 18 OHM 1A", Case Code (Imperial)=0603, Case Code (Metric)=1608, Current=1A, DC Resistance (DCR)=4mR, Manufacturer="Taiyo Yuden", Max DC Current=7.5A, Max Operating Temperature=125°C, Min Operating Temperature=-40°C, Package Quantity=1, Test Frequency=100MHz, Tolerance=30%
L1V: library part I0051-A.3, "IND FIXED SMD 0603 2.2uH, 20%,", DC Resistance (DCR)=250mR, Manufacturer=Murata, Max Operating Temperature=85°C, Min Operating Temperature=-40°C, Test Frequency=1MHz, Tolerance=20%
PB1 PB2: library part B0006-A.7, "PUSHBUTTON SMD PTS820 NO HOLES", Color=Black, Manufacturer=C&K, Max Operating Temperature=85°C, Min Operating Temperature=-40°C
R1 R4 R6 R48: library part R0001-A.8, "RES CHIP 0402 100K 1% 1/16W", Case Code (Imperial)=0402, Case Code (Metric)=1005, Manufacturer=Vishay, Manufacturer 2=Panasonic, Manufacturer Part Number 2=ERJ-2RKF1003X, Power=63mW, Tolerance=1%
R2: library part R0154-A.2, "RES CHIP 0201 8.06kR 1/20W 1%", Case Code (Imperial)=0201, Case Code (Metric)=0603, Manufacturer=Yageo, Power=50mW, Tolerance=1%
R3 R7 R8 R44 R45: library part R0000-A.8, "RES CHIP 0402 0R 1/16W", Case Code (Imperial)=0402, Case Code (Metric)=1005, Manufacturer=Vishay, Manufacturer 2=Panasonic, Manufacturer Part Number 2=ERJ-S020R00X, Power=63mW, Tolerance=J
R9 R10 R11 R12: library part R0131-A.3, "RES CHIP 0805 0R 1/8W", Case Code (Imperial)=0805, Case Code (Metric)=2012, Manufacturer=Vishay, Power=125mW, Tolerance=J
R34 R35: library part R0166-A.4, "RES CHIP 0402 2K 5% 1/16W", Case Code (Imperial)=0402, Case Code (Metric)=1005, Manufacturer=Vishay, Manufacturer 2=Panasonic, Manufacturer Part Number 2=ERJ-2GEJ202X, Power=63mW, Tolerance=1%
R46: library part R0003-A.8, "RES CHIP 0402 10K 1% 1/16W", Case Code (Imperial)=0402, Case Code (Metric)=1005, Manufacturer=Vishay, Manufacturer 2=Panasonic, Manufacturer Part Number 2=ERJ-2RKF1002X, Power=63mW, Tolerance=1%
U1: library part U0020-A.5, "IC MCU Cortex M7 + Cortex M4", Manufacturer=STMicroelectronics
U1V: library part U0008-A.14, "MODULE WiFi 11b/g/n+BLUETOOTH 4.2 SHIELDED ULTRA SMALL LBEE5KL1DX", Case/Package=SMD/SMT, Current - Receiving=60mA, Current - Transmitting=370mA, Frequency=2.4GHz, Manufacturer=Murata, Max Operating Temperature=70°C, Min Operating Temperature=-30°C
U2: library part U0053-A.4, "IC CODEC STER HDPN & SPKR 40QFN", Case/Package=QFN, Manufacturer="Cirrus Logic", Max Operating Temperature=85°C, Min Operating Temperature=-40°C, Operating Supply Voltage=2.5V, Package Quantity=50
U2: library part U0122-A.2, "IC SDRAM 64 Mb PC133 SDR", Case/Package=TFBGA, Frequency=166MHz, Manufacturer="Alliance Memory", Max Operating Temperature=85°C, Min Operating Temperature=-40°C
U3: library part U0121-A.4, "IC TXRX USB 2.0 FLEXPWR 32QFN", Case/Package=QFN, Frequency=60MHz, Manufacturer=Microchip, Max Operating Temperature=85°C, Max Supply Voltage=2V, Min Operating Temperature=-40°C, Min Supply Voltage=1.6V, Operating Supply Current=18uA, Operating Supply Voltage=5.5V, Package Quantity=4000
U4: library part U0120-A.2, "IC FLASH S-NOR 128M", Manufacturer=Macronix

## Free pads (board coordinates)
  round 3.2 hole 3.2 unplated: MH1(96.52,2.54) MH2(15.24,50.8) MH3(90.17,50.8) MH4(13.996,2.553) MH5(66.04,35.56) MH6(66.066,7.633)

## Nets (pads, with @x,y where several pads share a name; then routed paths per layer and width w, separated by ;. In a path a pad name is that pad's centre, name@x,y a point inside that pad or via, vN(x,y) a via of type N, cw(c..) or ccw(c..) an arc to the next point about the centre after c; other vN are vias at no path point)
+1V8: C24.2@33.48,16.74 C25.2@29.496,20.655 C26.2@30.826,16.155 C27.2@30.826,13.905 C28.2@29.496,18.405 C41.2 C42.2 U2.13 U2.16 U2.34 U3.28 U3.30 | length 1.6
  TOP w0.127: 85.66,39.961 87.26,39.961
+3V1: C78.2 U1.N17 U1.P17 U4.8
+3V1SW: C3.2 C4.2 C5.2 C6.2 C7.2 C8.2 C9.2 C10.2 C13.2 C15.2 C16.2 C17.2 C18.2 C19.2 C20.2 C21.2 C22.2 C23.2 C24.2@55.532,38.883 C28.2@52.625,40.71 C29.2 C36.2@42.155,15.52 C37.2@46.34,21.41 C51.2@51.563,23.24 C52.2 C53.2 C73.2 C75.2 C76.2 C77.2 R4.1 R8.1 R11.2 R12.2 R48.2 U1.A6 U1.C17 U1.E6 U1.E9 U1.E11 U1.F5 U1.F17 U1.G5 U1.G13 U1.H5 U1.H13 U1.J13 U1.K5 U1.K13 U1.L5 U1.L13 U1.M5 U1.M13 U1.N7 U1.N8 U1.N10 U1.N11 U1.N12 U1.U12 U2.A7 U2.A9 U2.B3 U2.C7 U2.D3 U2.E7 U2.J9 U3.8 U3.11 U3.20 U3.21 U3.32 | length 1.6
  TOP w0.127: 85.66,39.707 87.26,39.707
+3V3: C35.2 C36.2@29.496,13.905 C37.2@32.156,20.655 C43.2 R34.1 R35.1 U2.5 U2.8 U2.33
AIN2A: U2.25
AIN2B: U2.26
AIN3A: U2.23
AIN3B: U2.24
BLE_CTRL_DEVICE_WAKE: 
BLE_CTRL_HOST_WAKE: 
BLE_CTRL_ON: 
DSI_CK_N: U1.L17
DSI_CK_P: U1.L16
DSI_D0_N: U1.M17
DSI_D0_P: U1.M16
DSI_D1_N: U1.K17
DSI_D1_P: U1.K16
GND: C1.1 C3.1 C4.1 C5.1 C6.1 C7.1 C8.1 C9.1 C10.1 C12.1 C13.1 C15.1 C16.1 C17.1 C18.1 C19.1 C20.1 C21.1 C22.1 C23.1 C24.1 C25.1 C26.1 C27.1 C28.1 C29.1 C30.1 C33.2 C35.1 C36.1 C37.1 C41.1 C42.1 C43.1 C46.2 C48.2 C49.2 C50.2 C51.1 C52.1 C53.1 C73.1 C75.1 C76.1 C77.1 C78.1 R1.2 R2.2 R6.2 R10.1 U1.A1 U1.A17 U1.B2 U1.B6 U1.C10 U1.C13 U1.C16 U1.F1 U1.F2 U1.G2 U1.G7 U1.G8 U1.G9 U1.G10 U1.G11 U1.G16 U1.H7 U1.H8 U1.H9 U1.H10 U1.H11 U1.J3 U1.J7 U1.J8 U1.J9 U1.J10 U1.J11 U1.J16 U1.J17 U1.K7 U1.K8 U1.K9 U1.K10 U1.K11 U1.K15 U1.L7 U1.L8 U1.L9 U1.L10 U1.L11 U1.L15 U1.M15 U1.N16 U1.P1 U1.R4 U1.R8 U1.T12 U1.U1 U1.U17 U2.3 U2.17 U2.35 U2.41 U2.A1 U2.A3 U2.B7 U2.C3 U2.D7 U2.E3 U2.J1 U3.14 U3.33 U4.4
HP/LINE_OUTA: U2.15
HP/LINE_OUTB: U2.14
HSU_D_N: R45.1 U3.19
HSU_D_P: R44.1 U3.18
MICBIAS: C51.2@30.826,18.405 U2.20
NetAUDIO_RST_X: AUDIO_RST.X U2.32
NetC1_2: C1.2 R3.2 U1.J2
NetC1V_1: 
NetC2V_1: 
NetC5V_1: 
NetC12_2: C12.2 R7.2 U1.C2
NetC30_2: C30.2 L1.1 R9.2 U1.L1
NetC31_1: C31.1 U2.12
NetC31_2: C31.2 U2.11
NetC33_1: C33.1 U2.10
NetC46_1: C46.1 U2.27
NetC48_1: C48.1 U2.18
NetC49_1: C49.1 U2.19
NetC50_1: C50.1 U2.28
NetL1_2: L1.2 R11.1
NetL1V_1: 
NetR2_1: R2.1 U3.24
NetR3_1: R3.1
NetR4_2: R4.2 U1.E7
NetR6_1: R6.1 U1.E8
NetR7_1: R7.1
NetR8_2: R8.2 U1.G17
NetR9_1: R9.1 U1.M1
NetR10_2: R10.2 U1.N1
NetR12_1: R12.1 U1.B1
NetR34_2: R34.2 U2.2
NetR35_2: R35.2 U2.1
NetR46_1: R46.1 U3.22
NetR46_2: R46.2
NetU1_J1: U1.J1
NetU1_K1: U1.K1
NetU1V_2: 
NetU1V_3: 
NetU1V_4: 
NetU1V_5: 
NetU1V_8: U2.40
NetU1V_9: U2.39
NetU1V_10: U2.36
NetU1V_11: U2.38
NetU1V_20: 
NetU1V_22: 
NetU1V_23: 
NetU1V_24: 
NetU1V_25: 
NetU1V_26: 
NetU1V_37: 
NetU2_37: U2.37
NetU3_26: U3.26
PA0: U1.N5
PA1: U1.N4
PA2: U1.N3
PA3: U1.U2 U3.3
PA4: U1.U3
PA5: U1.T3 U3.1
PA6: U1.R3
PA7: U1.R5
PA8: U1.E15
PA9: U1.D15
PA10: U1.D14
PA11: U1.E17
PA12: U1.E16
PA13: U1.C15
PA14: U1.B14
PA15: U1.A14
PB0: U1.U5 U3.4
PB1: U1.T5 U3.5
PB2: U1.R6
PB3: U1.C6
PB4: U1.B7
PB5: U1.A5 U3.13
PB6: U1.B5
PB7: U1.C5
PB8: U1.D5
PB9: U1.D4
PB10: U1.P11 U3.6
PB11: U1.P12 U3.7
PB12: U1.T14 U3.9
PB13: U1.U14 U3.10
PB14: U1.U15
PB15: U1.T15
PC0: U1.L2 U3.29
PC1: U1.M2
PC2: U1.M3
PC3: U1.M4
PC4: U1.T4
PC5: U1.U4
PC6: U1.F14
PC7: U1.F13
PC8: U1.E13
PC9: U1.E14
PC10: U1.A13
PC11: U1.B13
PC12: U1.C12
PC13: U1.E3
PD0: U1.D13 U2.C9
PD1: U1.E12 U2.B8
PD2: U1.D12
PD3: U1.B12
PD4: U1.A12
PD5: U1.A11
PD6: U1.B11
PD7: U1.C11
PD8: U1.U16 U2.B2
PD9: U1.T17 U2.B1
PD10: U1.T16 U2.A2
PD11: U1.R15 U4.5
PD12: U1.R16 U4.2
PD13: U1.R17 U4.7
PD14: U1.P16 U2.A8
PD15: U1.P15 U2.B9
PE0: U1.C4 U2.E8
PE1: U1.B4 U2.F1
PE2: U1.C3
PE3: U1.D3
PE4: U1.D2
PE5: U1.D1
PE6: U1.E5
PE7: U1.U9 U2.C8
PE8: U1.T9 U2.D9
PE9: U1.P9 U2.D8
PE10: U1.N9 U2.E9
PE11: U1.P10 U2.E1
PE12: U1.R10 U2.D2
PE13: U1.T10 U2.D1
PE14: U1.U10 U2.C2
PE15: U1.R11 U2.C1
PF0: U1.G4 U2.H7
PF1: U1.G3 U2.H8
PF2: U1.G1 U2.J8
PF3: U1.H4 U2.J7
PF4: U1.J5 U2.J3
PF5: U1.J4 U2.J2
PF6: U1.K2
PF7: U1.K3 U4.3
PF8: U1.K4
PF9: U1.L4
PF10: U1.L3 U4.6
PF11: U1.T7 U2.F8
PF12: U1.R7 U2.H3
PF13: U1.P7 U2.H2
PF14: U1.P8 U2.H1
PF15: U1.R9 U2.G3
PG0: U1.T8 U2.H9
PG1: U1.U8 U2.G2
PG2: U1.H16 U2.G1
PG3: U1.H15
PG4: U1.H14 U2.G7
PG5: U1.G14 U2.G8
PG6: U1.G15 U4.1
PG7: U1.F16
PG8: U1.F15 U2.F2
PG9: U1.A10
PG10: U1.A9
PG11: U1.B9
PG12: U1.C9
PG13: U1.D9
PG14: U1.D8
PG15: U1.D6 U2.F7
PH2: U1.N2 U2.F3
PH3: U1.P2 U2.G9
PH4: U1.P3 U3.2
PH5: U1.P4 U2.F9
PH6: U1.T11
PH7: U1.U13
PH8: U1.T13
PH9: U1.R13
PH10: U1.P13
PH11: U1.P14
PH12: U1.R14
PH13: U1.D16
PH14: U1.B17
PH15: U1.B16
PI0: U1.A16
PI1: U1.A15
PI2: U1.B15
PI3: U1.C14
PI4: U1.A4
PI5: U1.A3
PI6: U1.A2
PI7: U1.B3
PI8: U1.E4
PI9: U1.E2
PI10: U1.F3
PI11: U1.F4 U3.31
PI12: U1.H1
PI13: U1.H2
PI14: U1.H3
PI15: U1.P5
PJ0: U1.N6
PJ1: U1.P6
PJ2: U1.T6
PJ3: U1.U6
PJ4: R1.1 R48.1 U1.U7 U3.27
PJ5: U1.R12
PJ6: U1.N15 U3.23
PJ7: U1.N14
PJ8: U1.N13
PJ9: U1.M14
PJ10: U1.L14
PJ11: U1.K14
PJ12: U1.D11
PJ13: U1.E10
PJ14: U1.D10
PJ15: U1.B10
PK0: U1.J14
PK1: U1.J15
PK2: U1.H17
PK3: U1.C8
PK4: U1.B8
PK5: U1.A8
PK6: U1.C7
PK7: U1.D7
SPKR/HP: U2.31
USB0_D_N: R45.2
USB0_D_P: R44.2
VCAP_A7: C27.2@47.84,40.71 U1.A7
VCAP_D17: C26.2@43.055,40.71 U1.D17
VCAP_U11: C25.2@42.54,24.11 U1.U11
WIFI_CTRL_HOST_WAKE: 
WIFI_CTRL_ON: 
pads on no net: "J10.SHIELD 1" "J10.SHIELD 2" "J10.SHIELD 3" "J10.SHIELD 4" "J11.SHIELD 1" "J11.SHIELD 2" "J11.SHIELD 3" "J11.SHIELD 4" C4V.1 C4V.2 C5V.1 C5V.2 Designator1.0 Designator1.1 Designator1.2 Designator1.3 Designator1.4 Designator1.5 Designator1.6 Designator1.7 Designator1.8 Designator1.9 Designator1.10 Designator1.11 Designator1.12 Designator1_1.1 Designator1_1.2 Designator1_1.3 Designator1_1.4 Designator1_1.5 Designator1_1.6 Designator1_1.7 Designator1_1.8 Designator1_1.9 Designator1_1.10 Designator2.1 Designator2.2 Designator2.3 Designator2.4 Designator2.5 Designator2.6 Designator2.7 Designator2.8 Designator2.9 Designator2.10 Designator3.1 Designator3.2 Designator3.3 Designator3.4 Designator3.5 Designator3.6 Designator3.7 Designator3.8 Designator3.9 Designator3.10 Designator4.1 Designator4.2 Designator4.3 Designator4.4 Designator4.5 Designator4.6 Designator4.7 Designator4.8 Designator4.9 Designator4.10 J1.1 J1.2 J1.3 J1.4 J1.5 J1.6 J1.7 J1.8 J1.9 J1.10 J1V.GND J1V.SIG J2.1 J2.2 J2.3 J2.4 J2.5 J2.6 J2.7 J2.8 J3.1 J3.2 J3.3 J3.4 J3.5 J3.6 J3.7 J3.8 J4.1 J4.2 J4.3 J4.4 J4.5 J4.6 J4.7 J4.8 J4.9 J4.10 J4.11 J4.12 J4.13 J4.14 J4.15 J4.16 J4.17 J4.18 J4.19 J4.20 J4.21 J4.22 J4.23 J4.24 J4.25 J4.26 J4.27 J4.28 J4.29 J4.30 J4.31 J4.32 J4.33 J4.34 J4.35 J4.36 J5.1 J5.2 J5.3 J5.4 J5.5 J5.6 J6.1 J6.2 J6.3 J6.4 J6.5 J6.6 J6.7 J6.8 J7.1 J7.2 J7.3 J7.4 J7.5 J7.6 J7.7 J7.8 J8.1 J8.2 J8.3 J8.4 J8.5 J8.6 J8.7 J8.8 J10.0 J10.A1 J10.A2 J10.A3 J10.A4 J10.A5 J10.A6 J10.A7 J10.A8 J10.A9 J10.A10 J10.A11 J10.A12 J10.B1 J10.B2 J10.B3 J10.B4 J10.B5 J10.B6 J10.B7 J10.B8 J10.B9 J10.B10 J10.B11 J10.B12 J11.0 J11.A1 J11.A2 J11.A3 J11.A4 J11.A5 J11.A6 J11.A7 J11.A8 J11.A9 J11.A10 J11.A11 J11.A12 J11.B1 J11.B2 J11.B3 J11.B4 J11.B5 J11.B6 J11.B7 J11.B8 J11.B9 J11.B10 J11.B11 J11.B12 J12.1 J12.2 J12.3 J12.4 J12.5 J12.6 J12.7 J12.8 J12.9 J12.10 J19.1 J19.2 J19.3 J19.4 J19.NC1 J19.NC2 J20.1 J20.2 J20.3 J20.4 L1V.1 L1V.2 PB1.5 PB1.6 PB1.PAD PB2.5 PB2.6 PB2.PAD U1.C1 U1.E1 U1.R1 U1.R2 U1.T1 U1.T2 U1V.1 U1V.2 U1V.3 U1V.4 U1V.5 U1V.6 U1V.7 U1V.8 U1V.9 U1V.10 U1V.11 U1V.12 U1V.13 U1V.14 U1V.15 U1V.16 U1V.17 U1V.18 U1V.19 U1V.20 U1V.21 U1V.22 U1V.23 U1V.24 U1V.25 U1V.26 U1V.27 U1V.28 U1V.29 U1V.30 U1V.31 U1V.32 U1V.33 U1V.34 U1V.35 U1V.36 U1V.37 U1V.38 U1V.39 U1V.40 U1V.41 U1V.42 U1V.43 U1V.44 U1V.45 U1V.46 U2.4 U2.6 U2.7 U2.9 U2.21 U2.22 U2.29 U2.30 U2.E2 U3.12 U3.15 U3.16 U3.17 U3.25 U4.9
copper on no net: | length 108.2
  TOP w0.127: 85.66,40.215 87.26,40.215 ; 85.66,40.469 87.26,40.469 ; 85.66,40.723 87.26,40.723 ; 85.66,40.977 87.26,40.977 ; 85.66,41.231 87.26,41.231 ; 85.66,41.485 87.26,41.485 ; 85.66,41.739 87.26,41.739 ; 85.66,41.993 87.26,41.993 ; 85.66,42.247 87.26,42.247 ; 85.66,42.501 87.26,42.501 ; 85.66,42.755 87.26,42.755 ; 85.66,43.009 87.26,43.009 ; 85.66,43.263 87.26,43.263 ; 85.66,43.517 87.26,43.517 ; 85.66,43.771 87.26,43.771 ; 85.66,44.025 87.26,44.025 ; 85.66,44.279 87.26,44.279 ; 85.66,44.533 87.26,44.533 ; 85.66,44.787 87.26,44.787 ; 85.66,45.041 87.26,45.041 ; 85.66,45.295 87.26,45.295 ; 85.66,45.549 87.26,45.549 ; 85.66,45.803 87.26,45.803 ; 85.66,46.057 87.26,46.057 ; 85.66,46.311 87.26,46.311 ; 85.66,46.565 87.26,46.565 ; 85.66,46.819 87.26,46.819 ; 85.66,47.073 87.26,47.073
  BOTTOM w0.127: 71.56,23.937 84.9,23.937 86.36,25.397 ; 85.66,39.739 87.26,39.739 ; 85.66,39.993 87.26,39.993 ; 85.66,40.247 87.26,40.247 ; 85.66,40.501 87.26,40.501 ; 85.66,40.755 87.26,40.755 ; 85.66,41.009 87.26,41.009 ; 85.66,41.263 87.26,41.263 ; 85.66,41.517 87.26,41.517 ; 85.66,41.771 87.26,41.771 ; 85.66,42.025 87.26,42.025 ; 85.66,42.279 87.26,42.279 ; 85.66,42.533 87.26,42.533 ; 85.66,42.787 87.26,42.787 ; 85.66,43.041 87.26,43.041 ; 85.66,43.295 87.26,43.295 ; 85.66,43.549 87.26,43.549 ; 85.66,43.803 87.26,43.803 ; 85.66,44.057 87.26,44.057 ; 85.66,44.311 87.26,44.311 ; 85.66,44.565 87.26,44.565 ; 85.66,44.819 87.26,44.819 ; 85.66,45.073 87.26,45.073 ; 85.66,45.327 87.26,45.327 ; 85.66,45.581 87.26,45.581 ; 85.66,45.835 87.26,45.835 ; 85.66,46.089 87.26,46.089 ; 85.66,46.343 87.26,46.343 ; 85.66,46.597 87.26,46.597 ; 85.66,46.851 87.26,46.851 ; 85.66,47.105 87.26,47.105

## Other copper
TOP:
  text "30 tracks / 5mil/5mil" at 77.66,41.739 h0.8

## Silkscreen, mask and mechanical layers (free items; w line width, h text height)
Top Overlay:
  drawing of 37 lines, arcs and shapes, not listed
  text "22" at 90.67,47.494 h1.8
  text "13" at 29.747,47.279 h1.8 r90
  text "RESET" at 1.483,47.109 h1.3
  text "7" at 46.485,47.083 h1.8 r90
  text "6" at 49.025,47.083 h1.8 r90
  text "5" at 51.565,47.083 h1.8 r90
  text "4" at 54.105,47.083 h1.8 r90
  text "3" at 56.645,47.083 h1.8 r90
  text "2" at 59.185,47.083 h1.8 r90
  text "1" at 61.725,47.083 h1.8 r90
  text "0" at 64.265,47.083 h1.8 r90
  text "14" at 69.345,47.083 h1.8 r90
  text "15" at 71.885,47.083 h1.8 r90
  text "16" at 74.425,47.083 h1.8 r90
  text "17" at 76.965,47.083 h1.8 r90
  text "18" at 79.505,47.083 h1.8 r90
  text "19" at 82.045,47.083 h1.8 r90
  text "20" at 84.585,47.083 h1.8 r90
  text "21" at 87.125,47.083 h1.8 r90
  text "12" at 32.214,45.282 h1.8 r90
  text "SCL1" at 19.514,45.098 h1.8 r90
  text "11" at 34.754,45.103 h1.8 r90
  text "10" at 37.294,45.103 h1.8 r90
  text "9" at 39.834,45.103 h1.8 r90
  text "8" at 42.374,45.103 h1.8 r90
  text "24" at 90.67,44.954 h1.8
  text "SDA1" at 22.054,44.918 h1.8 r90
  text "GND" at 27.192,44.897 h1.8 r90
  text "AREF" at 24.594,44.587 h1.8 r90
  text "26" at 90.67,42.414 h1.8
  text "28" at 90.67,39.874 h1.8
  text "BOOT0" at 62.093,37.473 h1.8
  text "54" at 70.25,37.333 h1.8
  text "55" at 77.87,37.333 h1.8
  text "72" at 80.41,37.333 h1.8
  text "73" at 88.03,37.333 h1.8
  text "30" at 90.67,37.334 h1.8
  text "31" at 98.19,37.334 h1.8
  text "56" at 70.25,34.793 h1.8
  text "57" at 77.84,34.793 h1.8
  text "32" at 90.67,34.794 h1.8
  text "33" at 98.19,34.794 h1.8
  text "88" at 10.56,32.254 h1.8
  text "89" at 20.72,32.254 h1.8
  text "58" at 70.25,32.253 h1.8
  text "59" at 77.84,32.253 h1.8
  text "74" at 80.41,32.253 h1.8
  text "75" at 88,32.253 h1.8
  text "34" at 90.67,32.254 h1.8
  text "35" at 98.19,32.254 h1.8
  text "76" at 80.41,29.713 h1.8
  text "77" at 88,29.713 h1.8
  text "36" at 90.67,29.714 h1.8
  text "37" at 98.19,29.714 h1.8
  text "61" at 77.845,27.423 h1.8
  text "90" at 10.56,27.174 h1.8
  text "91" at 20.83,27.174 h1.8
  text "60" at 70.25,27.173 h1.8
  text "78" at 80.41,27.173 h1.8
  text "79" at 88.03,27.173 h1.8
  text "38" at 90.67,27.174 h1.8
  text "39" at 98.19,27.174 h1.8
  text "63" at 77.84,24.886 h1.8
  text "92" at 10.56,24.634 h1.8
  text "93" at 20.72,24.634 h1.8
  text "64" at 70.25,24.633 h1.8
  text "40" at 90.67,24.634 h1.8
  text "41" at 98.19,24.634 h1.8
  text "66" at 70.25,22.093 h1.8
  text "65" at 77.84,22.093 h1.8
  text "80" at 80.41,22.093 h1.8
  text "81" at 88,22.093 h1.8
  text "42" at 90.67,22.094 h1.8
  text "43" at 98.19,22.094 h1.8
  text "5V" at 10.462,19.554 h1.8
  text "3V3" at 20.72,19.554 h1.8
  text "94" at 59.195,19.554 h1.4
  text "95" at 68.545,19.554 h1.4
  text "82" at 80.41,19.553 h1.8
  text "83" at 88,19.553 h1.8
  text "44" at 90.67,19.554 h1.8
  text "45" at 98.19,19.554 h1.8
  text "96" at 59.195,17.013 h1.4
  text "97" at 68.545,17.013 h1.4
  text "68" at 70.25,17.013 h1.8
  text "67" at 77.87,17.013 h1.8
  text "84" at 80.41,17.013 h1.8
  text "87" at 88,17.013 h1.8
  text "46" at 90.67,17.014 h1.8
  text "47" at 98.19,17.014 h1.8
  text "98" at 59.195,14.473 h1.4
  text "99" at 68.545,14.473 h1.4
  text "70" at 70.25,14.473 h1.8
  text "69" at 77.84,14.473 h1.8
  text "48" at 90.67,14.474 h1.8
  text "49" at 98.19,14.474 h1.8
  text "50" at 90.67,11.934 h1.8
  text "51" at 98.19,11.934 h1.8
  text "52" at 90.67,9.394 h1.8
  text "53" at 98.19,9.394 h1.8
  text "GIGA" at 49.699,7.897 h4
  text "GND" at 93.98,6.869 h1.6
  text "SPKA+" at 18.545,4.349 h1.8 r90
  text "SPKA-" at 21.085,4.349 h1.8 r90
  text "SPKB+" at 23.625,4.349 h1.8 r90
  text "SPKB-" at 26.165,4.349 h1.8 r90
  text "NTC VBAT" at 29.243,4.349 h1.8 r90
  text "IOREF" at 31.245,4.349 h1.8 r90
  text "RESET" at 33.785,4.349 h1.8 r90
  text "3V3" at 36.325,4.349 h1.8 r90
  text "5V" at 38.865,4.349 h1.8 r90
  text "VIN" at 46.485,4.349 h1.8 r90
  text "A0" at 51.565,4.349 h1.8 r90
  text "A1" at 54.105,4.349 h1.8 r90
  text "A2" at 56.645,4.349 h1.8 r90
  text "A3" at 59.185,4.349 h1.8 r90
  text "A4" at 61.725,4.349 h1.8 r90
  text "A5" at 64.265,4.349 h1.8 r90
  text "A6" at 66.805,4.349 h1.4 r90
  text "A7" at 69.345,4.349 h1.8 r90
  text "A8" at 74.425,4.349 h1.8 r90
  text "A9" at 76.965,4.349 h1.8 r90
  text "A10" at 79.505,4.349 h1.8 r90
  text "A11" at 82.045,4.349 h1.8 r90
  text "DAC2" at 84.585,4.349 h1.8 r90
  text "DAC1" at 87.125,4.349 h1.8 r90
  text "CANRX" at 89.665,4.349 h1.5 r90
  text "CANTX" at 92.205,4.349 h1.5 r90
  text "GND" at 41.416,2.553 h1.8 r90
  text "GND" at 43.956,2.553 h1.8 r90
  text "AUDIO IN/OUT" at 0.131,1.991 h1.8
Route Tool Path:
  lines w2: -1,29.75 -1,22.47 -1,1 ccw(c1,1) 1,-1 42.3,-1 48.8,-1 ; -1,33.75 -1,40.25 -1,52.34 cw(c1,52.34) 1,54.34 41.52,54.34 48.8,54.34 ; 52.8,-1 60.08,-1 98.06,-1 ccw(c98.06,1) 100.06,1 100.06,2.126 102.307,4.373 ; 52.8,54.34 59.3,54.34 97.536,54.34 ; 102.6,19.096 102.6,12.596 102.6,5.08 ; 102.6,23.096 102.6,30.376 102.6,37.846 ; 97.536,54.34 cw(c97.536,53.34) 98.243,54.047 ; 97.536,54.34 cw(c97.536,53.34) 98.243,54.047 ; 98.243,54.047 99.767,52.523 ; 99.767,52.523 cw(c99.06,51.816) 100.06,51.816 ; 99.767,52.523 cw(c99.06,51.816) 100.06,51.816 ; 100.06,51.816 100.06,40.8 102.307,38.553 ; 102.307,4.373 ccw(c101.6,5.08) 102.6,5.08 ; 102.307,4.373 ccw(c101.6,5.08) 102.6,5.08 ; 102.307,38.553 cw(c101.6,37.846) 102.6,37.846 ; 102.307,38.553 cw(c101.6,37.846) 102.6,37.846
Board:
  the board outline again, w0.254
Mechanical 9:
  lines w0.1: 6.194,2.927 7.464,2.927 ; 7.464,1.657 7.464,2.927 ; 7.464,4.197 7.464,2.927 ; 8.734,2.927 7.464,2.927 ; 17.552,50.813 18.822,50.813 ; 18.822,49.543 18.822,50.813 ; 18.822,52.083 18.822,50.813 ; 20.092,50.813 18.822,50.813 ; 26.696,2.553 27.966,2.553 ; 27.966,1.283 27.966,2.553 ; 27.966,3.823 27.966,2.553 ; 29.236,2.553 27.966,2.553 ; 44.476,50.813 45.746,50.813 ; 45.746,49.543 45.746,50.813 ; 45.746,52.083 45.746,50.813 ; 47.016,50.813 45.746,50.813 ; 49.556,2.553 50.826,2.553 ; 50.826,1.283 50.826,2.553 ; 50.826,3.823 50.826,2.553 ; 52.096,2.553 50.826,2.553 ; 62.357,30.48 63.627,30.48 ; 63.627,29.21 63.627,30.48 ; 63.627,31.75 63.627,30.48 ; 64.897,30.48 63.627,30.48 ; 67.336,50.813 68.606,50.813 ; 68.606,49.543 68.606,50.813 ; 68.606,52.083 68.606,50.813 ; 69.876,50.813 68.606,50.813 ; 72.416,2.553 73.686,2.553 ; 73.686,1.283 73.686,2.553 ; 73.686,3.823 73.686,2.553 ; 74.956,2.553 73.686,2.553 ; 92.71,50.799 93.98,50.799 ; 93.98,49.529 93.98,50.799 ; 93.98,52.069 93.98,50.799 ; 95.25,50.799 93.98,50.799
